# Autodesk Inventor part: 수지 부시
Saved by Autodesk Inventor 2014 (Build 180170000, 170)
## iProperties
Created: 2024-11
Part Number: 수지 부시
Material: 일반
Document SubType Name: Modeling
Designer: dg
Density: 1 g/cm^3
Appearance: 기본값
Author: dg
Author: jhkim
Creation Date: 2024-10-25
Sending System: Autodesk Inventor 2025
Preprocessor: ST-DEVELOPER v20
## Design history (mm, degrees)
node "수지 부시1"
node "솔리드1"
node "기준1"
